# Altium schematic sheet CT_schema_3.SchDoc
size 204 x 169 mm
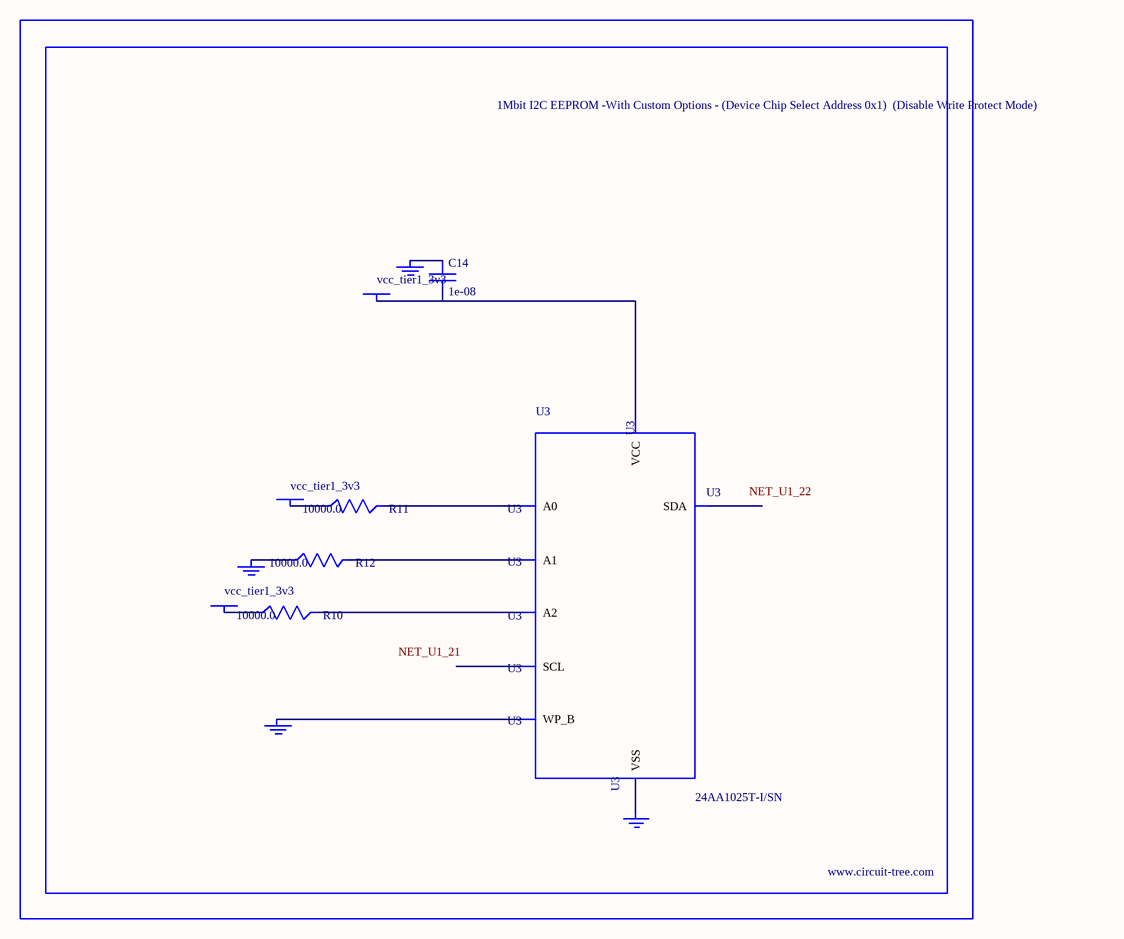
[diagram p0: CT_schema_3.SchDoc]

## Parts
BORDER2  (no value)
C14  1e-08  [C0402]
GND_INSTANCE_2_0  (no value)
GND_INSTANCE_2_1  (no value)
GND_INSTANCE_2_2  (no value)
GND_INSTANCE_2_3  (no value)
POWER_INSTANCE_2_0  vcc_tier1_3v3
POWER_INSTANCE_2_1  vcc_tier1_3v3
POWER_INSTANCE_2_2  vcc_tier1_3v3
R10  10000.0  [R0603]
R11  10000.0  [R0603]
R12  10000.0  [R0603]
U3  24AA1025T-I/SN  [SOIC-8]

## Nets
NetC14_1: C14.1 GND_INSTANCE_2_2.0(GND)
NetC14_2: C14.2 POWER_INSTANCE_2_2.0(PWR) U3.8(VCC)
NetGND_INSTANCE_2_0_0: GND_INSTANCE_2_0.0(GND) R12.1
NetGND_INSTANCE_2_1_0: GND_INSTANCE_2_1.0(GND) U3.7(WP_B)
NetGND_INSTANCE_2_3_0: GND_INSTANCE_2_3.0(GND) U3.4(VSS)
NetPOWER_INSTANCE_2_0_0: POWER_INSTANCE_2_0.0(PWR) R11.1
NetPOWER_INSTANCE_2_1_0: POWER_INSTANCE_2_1.0(PWR) R10.1
NetR10_2: R10.2 U3.3(A2)
NetR11_2: R11.2 U3.1(A0)
NetR12_2: R12.2 U3.2(A1)

Not connected (* = marked no-connect by the designer): U3 5(SDA) 6(SCL)

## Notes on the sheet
- Labels drawn without touching a wire or pin: NET_U1_21, NET_U1_22

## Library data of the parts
BORDER2 = BORDER_PAGE2
C14 = C0402C103K3RAC
GND_INSTANCE_2_0-GND_INSTANCE_2_3 = GND
POWER_INSTANCE_2_0-POWER_INSTANCE_2_2 = PWR
R10-R12 = RC0603JR-0710KL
